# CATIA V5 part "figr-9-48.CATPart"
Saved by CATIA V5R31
Part number: Part1
Bounding box of the stored display mesh (mm): x -53.419 to 50, y -50 to 50, z -57.709 to 133.109
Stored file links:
  D:\PROJECTS\Project 2021\US EDITION\CATIA V5 6R 2021\Resources\Part Files\c09_catia_v5_6r2021_prt\c09_catia_v5_6r2021_prt\figr-9-48.CATPart
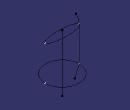
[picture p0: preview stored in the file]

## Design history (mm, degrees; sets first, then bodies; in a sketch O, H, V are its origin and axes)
Body1 (main body)
  Plane1: type Offset, RefPlane xy-plane, Offset 103
  Sketch1 on Plane1, origin (0, 0, 103), H (1, 0, 0), V (0, 1, 0)
    ellipse A1 centre (0, 0) semi-axes 50, 13.2069 rotation 0
    point P1 (50, 0)
    "Radius" A1 = 50
    coincidence: P1 H, A1 P1
  Extremum1: Reference Sketch1, Direction (1, 2, 3)
  Sketch2 on xy-plane, origin (0, 0, 0), H (1, 0, 0), V (0, 1, 0)
    circle A1 centre (0, 0) radius 50
    radius A1 = 50
  Extremum2: Reference Sketch2, Direction (1, 2, 3)
  Sketch3 on zx-plane, origin (0, 0, 0), H (-1, 0, 0), V (0, 0, 1)
    spline S1 through (37.7591, -31.0289) (41.8235, -21.251) (50, 0) (49.8084, 85.7657) (50, 103) (41.6255, 133.1089)
    reference projected line E1 (-50, 103) -> (50, 103) from Sketch1.A1
    point P1 (50, 0)
    point P2 (50, 103)
    distance V P1 = 50
    distance P2 V = 50
    coincidence: P1 H, P2 E1
  Sketch4 on zx-plane, origin (0, 0, 0), H (-1, 0, 0), V (0, 0, 1)
    line L1 (0, 111.062) -> (0, -57.7094)
    point P1 (0, 111.062)
    coincidence: P1 V
    vertical: L1 V
  Loft1: solid, Sections (Sketch1; Sketch2), Spine Sketch4, Guides Sketch3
